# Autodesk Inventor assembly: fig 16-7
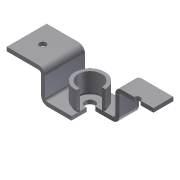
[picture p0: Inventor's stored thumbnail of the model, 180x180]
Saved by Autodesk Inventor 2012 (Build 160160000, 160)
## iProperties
Created: 2005-03
Part Number: fig 16-7
Document SubType Name: Weldment
Designer: CADCIM
Manufacturer: Standard
Standards Organization: Custom
Author: CADCIM
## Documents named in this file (3)
- C:\Users\CadCim\Documents\SAILESH\inventor-2011-fact-prt\c16-inv-2011-prt\c16_inv_2012_prt\fig 16-7\fig 16-7.iam
- C:\Users\CadCim\Documents\SAILESH\inventor-2011-fact-prt\c16-inv-2011-prt\fig-16-7\Bracket.ipt
- C:\Users\CadCim\Documents\SAILESH\inventor-2011-fact-prt\c16-inv-2011-prt\fig-16-7\cylinder.ipt
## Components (2 placed, 2 different names)
1. Bracket:1 — Insert:1
2. cylinder:1 — Insert:1
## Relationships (1: Insert 1)
- Insert:1: Bracket:1 ↔ cylinder:1
